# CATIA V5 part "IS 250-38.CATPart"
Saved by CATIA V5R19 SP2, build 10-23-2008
Part number: IS 250-38
Bounding box of the stored display mesh (mm): x -18.951 to 18.951, y -18.952 to 18.952, z 0 to 126
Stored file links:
  C:\Users\Bora\Desktop\3D Katı model\IS serisi\IS 250\IS 250-38.CATPart
  C:\Program Files\Dassault Systemes\B19\intel_a\reffiles\standard\MetricThickPitch.txt
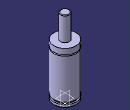
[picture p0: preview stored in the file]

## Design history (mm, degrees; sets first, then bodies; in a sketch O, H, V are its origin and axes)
Body1 (main body)
  Sketch1 on yz-plane, origin (0, 0, 0), H (0, 1, 0), V (0, 0, 1)
    point P3 (7.5, 125)
    point P5 (7.5, 125)
    point P7 (19, 76.5)
    point P8 (19, 74.5)
    point P12 (19, 74.5)
    point P13 (19, 76.5)
    line L1 (19, 0) -> (19, 4)
    line L2 (7.5, 125) -> (7.5, 86)
    arc A1 centre (6.5, 125) radius 1 from (7.5, 125) to (6.5, 126) ccw
    arc A2 centre (19, 75.5) radius 1 from (19, 76.5) to (19, 74.5) ccw
    line L3 (16.5, 7.5) -> (16.5, 4)
    line L4 (19, 7.5) -> (19, 74.5)
    line L5 (19, 76.5) -> (19, 86)
    line L6 (6.5, 126) -> (0, 126)
    point P15 (0, 126)
    line L7 (7.5, 86) -> (19, 86)
    line L8 (0, 0) -> (19, 0)
    line L9 (16.5, 4) -> (19, 4)
    line L10 (16.5, 7.5) -> (19, 7.5)
    tangency: L6 A1
    coincidence: P15 V, P3 P5, P7 P13, P8 P12
    horizontal: L7 H, L8 H, L9 H, L10 H
  Shaft1: profile Sketch1, axis Sketch1.V, angle 360
  Sketch2 on face of Shaft1 from Sketch1.L8, origin (0, 0, 0), H (1, 0, 0), V (0, -1, 0)
    point P1 (0, 0)
  Hole1: placed by Sketch2, at (0, 0, 0) direction (0, 0, 1), diameter 6.647, depth 7, threaded "M8", thread diameter 8, thread depth 7, pitch 1.25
